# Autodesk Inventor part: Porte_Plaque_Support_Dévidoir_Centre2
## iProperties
Created: 2009-01
Part Number: Porte_Plaque_Support_Dévidoir_Centre2
Document SubType Name: Sheet Metal
Designer: claivier
Author: claivier
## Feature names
1. Perçage1 [Hole]
2. Miroir1 [Mirror]
3. Plaque1
4. Pli1
5. Couper1
